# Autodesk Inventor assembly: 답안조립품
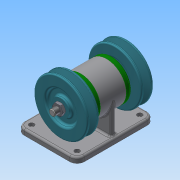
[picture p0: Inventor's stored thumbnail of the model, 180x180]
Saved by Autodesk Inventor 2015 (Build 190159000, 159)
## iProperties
Created: 2019-09
Part Number: 답안조립품
Document SubType Name: Assembly
Designer: user
Author: user
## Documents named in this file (10)
- C:\Users\user\Desktop\490904V1030\답안조립품.iam
- C:\Users\user\Desktop\490904V1030\본체.ipt
- C:\Users\user\Desktop\490904V1030\베어링 6004.ipt
- C:\Users\user\Desktop\490904V1030\축.ipt
- C:\Users\user\Desktop\490904V1030\커버.ipt
- C:\Users\user\Desktop\490904V1030\오일 실 17 30 5.ipt
- C:\Users\user\Desktop\490904V1030\키 5 x 5 x 12.ipt
- C:\Users\user\Desktop\490904V1030\V-벨트풀리.ipt
- C:\Users\user\Desktop\490904V1030\너트 M10x1.ipt
- C:\Users\user\Desktop\490904V1030\볼트 M4.ipt
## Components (2 placed, 1 different names)
1. V-벨트풀리:1 — 각도:1
2. V-벨트풀리:2 — 각도:2
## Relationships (2: Angle 2)
- 각도:1 [Angle]: V-벨트풀리:1
- 각도:2 [Angle]: V-벨트풀리:2
